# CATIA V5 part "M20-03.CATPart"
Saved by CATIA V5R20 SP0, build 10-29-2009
Part number: M20-03
Revision: ANY
Definition: UNKNOWN
Nomenclature: M20-03
Source: Unknown
Bounding box of the stored display mesh (mm): x 0 to 50, y -20 to 20, z 0 to 20
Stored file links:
  C:\Users\Utente\Desktop\IO LAVORO\3D X SITO CF\X 3D SITO CF 27-09-2020\740T\740T-20\M20-03.CATPart
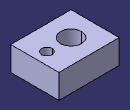
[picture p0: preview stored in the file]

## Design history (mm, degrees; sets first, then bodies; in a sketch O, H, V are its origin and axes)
Body1 "NONE" (main body)
  Solid1: solid without history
